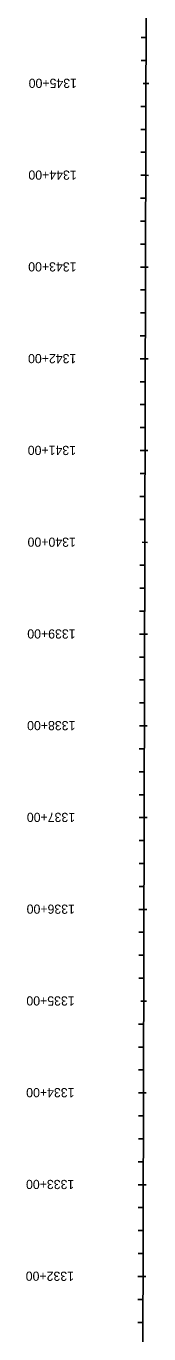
# Model space of a CAD drawing. Extents: x 14541681 to 14544384, y 8572153 to 8583558.
# Drawn here: x 14544132 to 14544265, y 8574996 to 8576421 of the extents above; entities that cross this region are included whole.
import ezdxf

# ---------------------------------------------------------------- set-up
doc = ezdxf.new("R2010")
doc.units = 0
for name, color, linetype in [('Alignment', 7, 'Continuous'), ('TextAlignmentLrg', 7, 'Continuous'), ('TextAlignmentSml', 7, 'Continuous')]:
    doc.layers.add(name, color=color, linetype=linetype)

msp = doc.modelspace()

# ---------------------------------------------------------------- linework, layer by layer
at = {"layer": 'Alignment'}
msp.add_line((14544251.8, 8572158.2), (14544263.9, 8577116.3), dxfattribs=at)
at = {"layer": 'TextAlignmentLrg'}
for p, q in [((14544259, 8576358.2), (14544265.1, 8576358.1)), ((14544261.8, 8576258.2), (14544256.4, 8576258.2)), ((14544261.6, 8576158.2), (14544256.1, 8576158.2)), ((14544261.3, 8576058.2), (14544255.9, 8576058.2)), ((14544261.1, 8575958.2), (14544255.6, 8575958.2)), ((14544257.8, 8575858.2), (14544263.9, 8575858.1)), ((14544260.6, 8575758.2), (14544255.1, 8575758.2)), ((14544260.4, 8575658.2), (14544254.9, 8575658.2)), ((14544260.1, 8575558.2), (14544254.7, 8575558.2)), ((14544259.9, 8575458.2), (14544254.4, 8575458.2)), ((14544256.6, 8575358.2), (14544262.7, 8575358.2)), ((14544259.4, 8575258.2), (14544253.9, 8575258.2)), ((14544259.1, 8575158.2), (14544253.7, 8575158.2)), ((14544258.9, 8575058.2), (14544253.4, 8575058.2))]:
    msp.add_line(p, q, dxfattribs=at)
at = {"layer": 'TextAlignmentSml'}
for p, q in [((14544262.2, 8576408.2), (14544256.7, 8576408.2)), ((14544262.1, 8576383.2), (14544256.7, 8576383.2)), ((14544259, 8576358.2), (14544265.1, 8576358.1)), ((14544262, 8576333.2), (14544256.5, 8576333.2)), ((14544261.9, 8576308.2), (14544256.5, 8576308.2)), ((14544261.9, 8576283.2), (14544256.4, 8576283.2)), ((14544258.8, 8576258.2), (14544264.9, 8576258.1)), ((14544261.8, 8576233.2), (14544256.3, 8576233.2)), ((14544261.7, 8576208.2), (14544256.2, 8576208.2)), ((14544261.6, 8576183.2), (14544256.2, 8576183.2)), ((14544258.5, 8576158.2), (14544264.6, 8576158.1)), ((14544261.5, 8576133.2), (14544256.1, 8576133.2)), ((14544261.5, 8576108.2), (14544256, 8576108.2)), ((14544261.4, 8576083.2), (14544255.9, 8576083.2)), ((14544258.3, 8576058.2), (14544264.4, 8576058.1)), ((14544261.3, 8576033.2), (14544255.8, 8576033.2)), ((14544261.2, 8576008.2), (14544255.8, 8576008.2)), ((14544261.2, 8575983.2), (14544255.7, 8575983.2)), ((14544258, 8575958.2), (14544264.2, 8575958.1)), ((14544261, 8575933.2), (14544255.6, 8575933.2)), ((14544261, 8575908.2), (14544255.5, 8575908.2)), ((14544260.9, 8575883.2), (14544255.5, 8575883.2)), ((14544257.8, 8575858.2), (14544263.9, 8575858.1)), ((14544260.8, 8575833.2), (14544255.3, 8575833.2)), ((14544260.7, 8575808.2), (14544255.3, 8575808.2)), ((14544260.7, 8575783.2), (14544255.2, 8575783.2)), ((14544257.5, 8575758.2), (14544263.7, 8575758.1)), ((14544260.5, 8575733.2), (14544255.1, 8575733.2)), ((14544260.5, 8575708.2), (14544255, 8575708.2)), ((14544260.4, 8575683.2), (14544255, 8575683.2)), ((14544257.3, 8575658.2), (14544263.4, 8575658.1)), ((14544260.3, 8575633.2), (14544254.8, 8575633.2)), ((14544260.2, 8575608.2), (14544254.8, 8575608.2)), ((14544260.2, 8575583.2), (14544254.7, 8575583.2)), ((14544257.1, 8575558.2), (14544263.2, 8575558.2)), ((14544260.1, 8575533.2), (14544254.6, 8575533.2)), ((14544260, 8575508.2), (14544254.5, 8575508.2)), ((14544259.9, 8575483.2), (14544254.5, 8575483.2)), ((14544256.8, 8575458.2), (14544262.9, 8575458.2)), ((14544259.8, 8575433.2), (14544254.4, 8575433.2)), ((14544259.8, 8575408.2), (14544254.3, 8575408.2)), ((14544259.7, 8575383.2), (14544254.2, 8575383.2)), ((14544256.6, 8575358.2), (14544262.7, 8575358.2)), ((14544259.6, 8575333.2), (14544254.1, 8575333.2)), ((14544259.5, 8575308.2), (14544254.1, 8575308.2)), ((14544259.4, 8575283.2), (14544254, 8575283.2)), ((14544256.3, 8575258.2), (14544262.4, 8575258.2)), ((14544259.3, 8575233.2), (14544253.9, 8575233.2)), ((14544259.3, 8575208.2), (14544253.8, 8575208.2)), ((14544259.2, 8575183.2), (14544253.7, 8575183.2)), ((14544256.1, 8575158.2), (14544262.2, 8575158.2)), ((14544259.1, 8575133.2), (14544253.6, 8575133.2)), ((14544259, 8575108.2), (14544253.6, 8575108.2)), ((14544259, 8575083.2), (14544253.5, 8575083.2)), ((14544255.8, 8575058.2), (14544262, 8575058.2)), ((14544258.8, 8575033.2), (14544253.4, 8575033.2)), ((14544258.8, 8575008.2), (14544253.3, 8575008.2))]:
    msp.add_line(p, q, dxfattribs=at)

# ---------------------------------------------------------------- texts
at = {"layer": 'TextAlignmentLrg'}
for s, p in [('1345+00', (14544187.1, 8576363.3)), ('1340+00', (14544185.9, 8575863.3)), ('1335+00', (14544184.6, 8575363.4))]:
    msp.add_text(s, height=10.02, rotation=179.8604, dxfattribs=at).set_placement(p)
at = {"layer": 'TextAlignmentSml'}
for s, p in [('1345+00', (14544187.1, 8576363.3)), ('1344+00', (14544186.8, 8576263.3)), ('1343+00', (14544186.6, 8576163.3)), ('1342+00', (14544186.4, 8576063.3)), ('1341+00', (14544186.1, 8575963.3)), ('1340+00', (14544185.9, 8575863.3)), ('1339+00', (14544185.6, 8575763.3)), ('1338+00', (14544185.4, 8575663.4)), ('1337+00', (14544185.1, 8575563.4)), ('1336+00', (14544184.9, 8575463.4)), ('1335+00', (14544184.6, 8575363.4)), ('1334+00', (14544184.4, 8575263.4)), ('1333+00', (14544184.2, 8575163.4)), ('1332+00', (14544183.9, 8575063.4))]:
    msp.add_text(s, height=10.02, rotation=179.8604, dxfattribs=at).set_placement(p)

doc.saveas('drawing.dxf')
